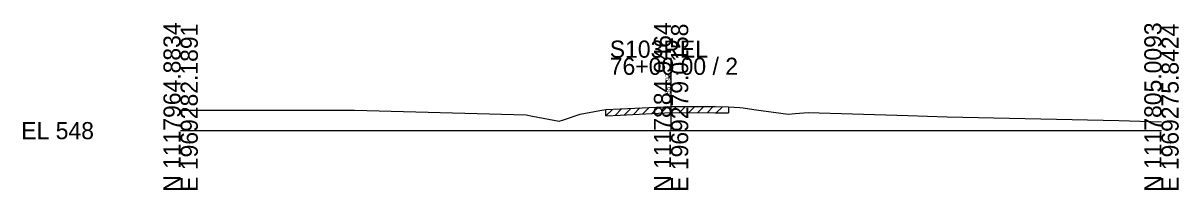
# Model space of a CAD drawing. Extents: x -26 to 163, y -10 to 24518.
# Drawn here: x -25.7 to 162.8, y 24490.3 to 24517.6 of the extents above; entities that cross this region are included whole.
import ezdxf

# ---------------------------------------------------------------- set-up
doc = ezdxf.new("R2010")
doc.units = 0
for name, color, linetype in [('RD_GPK_XS_Cell', 7, 'Continuous'), ('RD_XS_ExGround', 7, 'Continuous'), ('RD_XS_ExPaveRet', 7, 'Continuous'), ('RD_XS_TX_Elev_EX', 7, 'Continuous')]:
    doc.layers.add(name, color=color, linetype=linetype)

msp = doc.modelspace()

# ---------------------------------------------------------------- linework, layer by layer
at = {"layer": 'RD_GPK_XS_Cell'}
for p, q in [((80, 24500), (80, 24511.92)), ((0, 24500), (80, 24500)), ((80, 24500), (160, 24500))]:
    msp.add_line(p, q, dxfattribs=at)
at = {"layer": 'RD_XS_ExGround'}
msp.add_lwpolyline([(0, 24503.37), (27.98, 24503.36), (28.34, 24503.35), (56.38, 24502.57), (57.39, 24502.37), (61.75, 24501.53), (62.48, 24501.79), (65.16, 24502.71), (68.41, 24503.27), (69.38, 24503.43), (71.69, 24503.54), (80.03, 24503.97), (87.17, 24503.92), (89.36, 24503.9), (91.21, 24503.76), (91.76, 24503.72), (93.5, 24503.48), (99.11, 24502.68), (100.23, 24502.78), (102.39, 24502.97), (118.65, 24502.48), (125.05, 24502.28), (153.05, 24501.65), (160, 24501.46)], dxfattribs=at)
at = {"layer": 'RD_XS_ExPaveRet'}
for p, q in [((72.38, 24502.57), (73.43, 24503.63)), ((73.88, 24502.65), (74.93, 24503.71)), ((75.38, 24502.73), (76.43, 24503.79)), ((76.88, 24502.81), (77.93, 24503.86)), ((78.38, 24502.89), (79.43, 24503.94)), ((79.88, 24502.97), (80.88, 24503.97)), ((81.38, 24502.96), (82.37, 24503.96)), ((82.88, 24502.95), (83.87, 24503.95)), ((84.38, 24502.94), (85.37, 24503.94)), ((85.88, 24502.93), (86.87, 24503.93)), ((87.38, 24502.92), (88.37, 24503.91)), ((89.36, 24503.9), (89.36, 24502.9)), ((69.38, 24502.43), (70.43, 24503.48)), ((69.38, 24502.43), (69.38, 24503.43)), ((69.38, 24502.43), (71.69, 24502.54)), ((70.88, 24502.5), (71.93, 24503.55)), ((71.69, 24502.54), (80.03, 24502.97)), ((80.03, 24502.97), (87.17, 24502.92)), ((87.17, 24502.92), (89.36, 24502.9))]:
    msp.add_line(p, q, dxfattribs=at)

# ---------------------------------------------------------------- texts
at = {"layer": 'RD_GPK_XS_Cell'}
for s, p in [('N 1117964.8834', (0, 24490)), ('E 1969282.1891', (2.8, 24490)), ('N 1117884.9464', (80, 24490)), ('E 1969279.0158', (82.8, 24490)), ('N 1117805.0093', (160, 24490)), ('E 1969275.8424', (162.8, 24490))]:
    msp.add_text(s, height=2.8, rotation=90, dxfattribs=at).set_placement(p)
for s, p in [('S103REL', (70, 24511.92)), ('76+00.00 / 2', (70, 24509.12)), ('EL 548', (-26, 24498.6))]:
    msp.add_text(s, height=2.8, dxfattribs=at).set_placement(p)
at = {"layer": 'RD_XS_TX_Elev_EX'}
msp.add_text('551.97', height=0.8, rotation=90, dxfattribs=at).set_placement((79.9, 24505.97))

doc.saveas('drawing.dxf')
